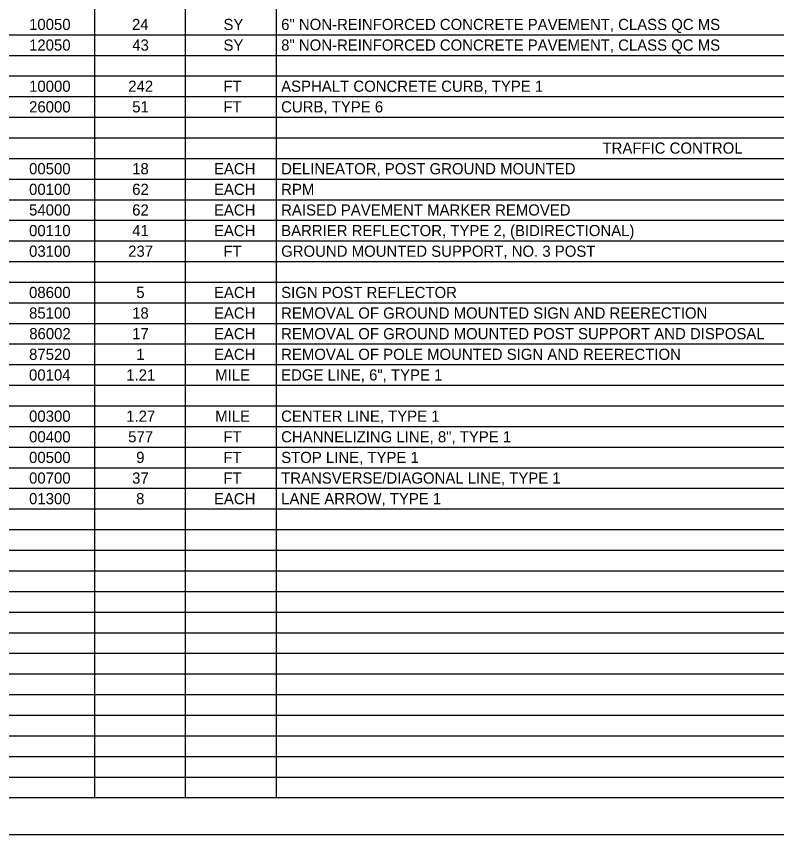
# Model space of a CAD drawing. Extents: x 0 to 34, y 0 to 22.
# Drawn here: x 16.98 to 27.3, y 0 to 11.11 of the extents above; entities that cross this region are included whole.
import ezdxf

# ---------------------------------------------------------------- set-up
doc = ezdxf.new("R2010")
doc.units = 0
for name, color, linetype in [('SH_Border', 7, 'Continuous'), ('SH_Cut_Line', 7, 'Continuous'), ('SH_Text', 7, 'Continuous')]:
    doc.layers.add(name, color=color, linetype=linetype)

msp = doc.modelspace()

# ---------------------------------------------------------------- linework, layer by layer
at = {"layer": 'SH_Border'}
msp.add_lwpolyline([(1.5, 21.5), (33.5, 21.5), (33.5, 0.5), (1.5, 0.5)], close=True, dxfattribs=at)
at = {"layer": 'SH_Cut_Line'}
msp.add_lwpolyline([(0, 0), (34, 0), (34, 22), (0, 22)], close=True, dxfattribs=at)
at = {"layer": 'SH_Text'}
for p, q in [((18.035, 21.5), (18.035, 0.502)), ((19.27, 21.5), (19.27, 0.502)), ((20.505, 21.5), (20.505, 0.502)), ((1.5, 10.861), (32, 10.861)), ((1.5, 10.581), (32, 10.581)), ((1.5, 10.301), (32, 10.301)), ((1.5, 10.021), (32, 10.021)), ((1.5, 9.741), (32, 9.741)), ((1.5, 9.461), (32, 9.461)), ((1.5, 9.181), (32, 9.181)), ((1.5, 8.901), (32, 8.901)), ((1.5, 8.621), (32, 8.621)), ((1.5, 8.342), (32, 8.342)), ((1.5, 8.062), (32, 8.062)), ((1.5, 7.782), (32, 7.782)), ((1.5, 7.502), (32, 7.502)), ((1.5, 7.222), (32, 7.222)), ((1.5, 6.942), (32, 6.942)), ((1.5, 6.662), (32, 6.662)), ((1.5, 6.382), (32, 6.382)), ((1.5, 6.102), (32, 6.102)), ((1.5, 5.822), (32, 5.822)), ((1.5, 5.542), (32, 5.542)), ((1.5, 5.262), (32, 5.262)), ((1.5, 4.982), (32, 4.982)), ((1.5, 4.702), (32, 4.702)), ((1.5, 4.422), (32, 4.422)), ((1.5, 4.142), (32, 4.142)), ((1.5, 3.862), (32, 3.862)), ((1.5, 3.582), (32, 3.582)), ((1.5, 3.302), (32, 3.302)), ((1.5, 3.022), (32, 3.022)), ((1.5, 2.742), (32, 2.742)), ((1.5, 2.462), (32, 2.462)), ((1.5, 2.182), (32, 2.182)), ((1.5, 1.902), (32, 1.902)), ((1.5, 1.622), (32, 1.622)), ((1.5, 1.342), (32, 1.342)), ((1.5, 1.062), (32, 1.062)), ((1.5, 0.782), (32, 0.782)), ((1.5, 0.502), (32, 0.502))]:
    msp.add_line(p, q, dxfattribs=at)

# ---------------------------------------------------------------- texts
for s, height, p in [('10050', 0.1515, (17.149, 10.925)), ('24', 0.1515, (18.546, 10.925)), ('SY', 0.1515, (19.788, 10.925)), ('6" NON-REINFORCED CONCRETE PAVEMENT, CLASS QC MS', 0.15151, (20.571, 10.925)), ('12050', 0.1515, (17.149, 10.645)), ('43', 0.1515, (18.55, 10.645)), ('SY', 0.1515, (19.788, 10.645)), ('8" NON-REINFORCED CONCRETE PAVEMENT, CLASS QC MS', 0.15151, (20.571, 10.645)), ('10000', 0.1515, (17.149, 10.086)), ('242', 0.1515, (18.495, 10.086)), ('FT', 0.1515, (19.786, 10.086)), ('ASPHALT CONCRETE CURB, TYPE 1', 0.15151, (20.571, 10.086)), ('26000', 0.1515, (17.149, 9.806)), ('51', 0.1515, (18.549, 9.806)), ('FT', 0.1515, (19.786, 9.806)), ('CURB, TYPE 6', 0.15151, (20.571, 9.806)), ('TRAFFIC CONTROL', 0.15151, (24.933, 9.246)), ('00500', 0.1515, (17.149, 8.966)), ('18', 0.1515, (18.548, 8.966)), ('EACH', 0.1515, (19.659, 8.966)), ('DELINEATOR, POST GROUND MOUNTED', 0.15151, (20.571, 8.966)), ('00100', 0.1515, (17.149, 8.686)), ('62', 0.1515, (18.549, 8.686)), ('EACH', 0.1515, (19.659, 8.686)), ('RPM', 0.1515, (20.571, 8.686)), ('54000', 0.1515, (17.149, 8.406)), ('62', 0.1515, (18.549, 8.406)), ('EACH', 0.1515, (19.659, 8.406)), ('RAISED PAVEMENT MARKER REMOVED', 0.15151, (20.571, 8.406)), ('00110', 0.1515, (17.149, 8.126)), ('41', 0.1515, (18.549, 8.126)), ('EACH', 0.1515, (19.659, 8.126)), ('BARRIER REFLECTOR, TYPE 2, (BIDIRECTIONAL)', 0.15151, (20.571, 8.126)), ('03100', 0.1515, (17.149, 7.846)), ('237', 0.1515, (18.494, 7.846)), ('GROUND MOUNTED SUPPORT, NO. 3 POST', 0.15151, (20.571, 7.846)), ('FT', 0.1515, (19.786, 7.846)), ('08600', 0.1515, (17.149, 7.286)), ('5', 0.152, (18.604, 7.286)), ('EACH', 0.1515, (19.659, 7.286)), ('SIGN POST REFLECTOR', 0.15151, (20.571, 7.286)), ('85100', 0.1515, (17.149, 7.006)), ('18', 0.1515, (18.548, 7.006)), ('EACH', 0.1515, (19.659, 7.006)), ('REMOVAL OF GROUND MOUNTED SIGN AND REERECTION', 0.15151, (20.571, 7.006)), ('86002', 0.1515, (17.151, 6.726)), ('17', 0.1515, (18.548, 6.726)), ('EACH', 0.1515, (19.659, 6.726)), ('REMOVAL OF GROUND MOUNTED POST SUPPORT AND DISPOSAL', 0.15151, (20.571, 6.726)), ('87520', 0.1515, (17.149, 6.446)), ('1', 0.152, (18.604, 6.446)), ('EACH', 0.1515, (19.659, 6.446)), ('REMOVAL OF POLE MOUNTED SIGN AND REERECTION', 0.15151, (20.571, 6.446)), ('00104', 0.1515, (17.148, 6.166)), ('1.21', 0.1515, (18.468, 6.166)), ('MILE', 0.1515, (19.676, 6.166)), ('EDGE LINE, 6", TYPE 1', 0.15151, (20.571, 6.166)), ('00300', 0.1515, (17.149, 5.606)), ('1.27', 0.1515, (18.467, 5.606)), ('MILE', 0.1515, (19.676, 5.606)), ('CENTER LINE, TYPE 1', 0.15151, (20.571, 5.606)), ('00400', 0.1515, (17.149, 5.326)), ('577', 0.1515, (18.494, 5.326)), ('FT', 0.1515, (19.786, 5.326)), ('CHANNELIZING LINE, 8", TYPE 1', 0.15151, (20.571, 5.326)), ('00500', 0.1515, (17.149, 5.046)), ('9', 0.152, (18.603, 5.046)), ('FT', 0.1515, (19.786, 5.046)), ('STOP LINE, TYPE 1', 0.15151, (20.571, 5.046)), ('00700', 0.1515, (17.149, 4.766)), ('37', 0.1515, (18.548, 4.766)), ('FT', 0.1515, (19.786, 4.766)), ('TRANSVERSE/DIAGONAL LINE, TYPE 1', 0.15151, (20.571, 4.766)), ('01300', 0.1515, (17.149, 4.486)), ('8', 0.152, (18.602, 4.486)), ('EACH', 0.1515, (19.659, 4.486)), ('LANE ARROW, TYPE 1', 0.15151, (20.571, 4.486))]:
    msp.add_text(s, height=height, dxfattribs=at).set_placement(p)

doc.saveas('drawing.dxf')
